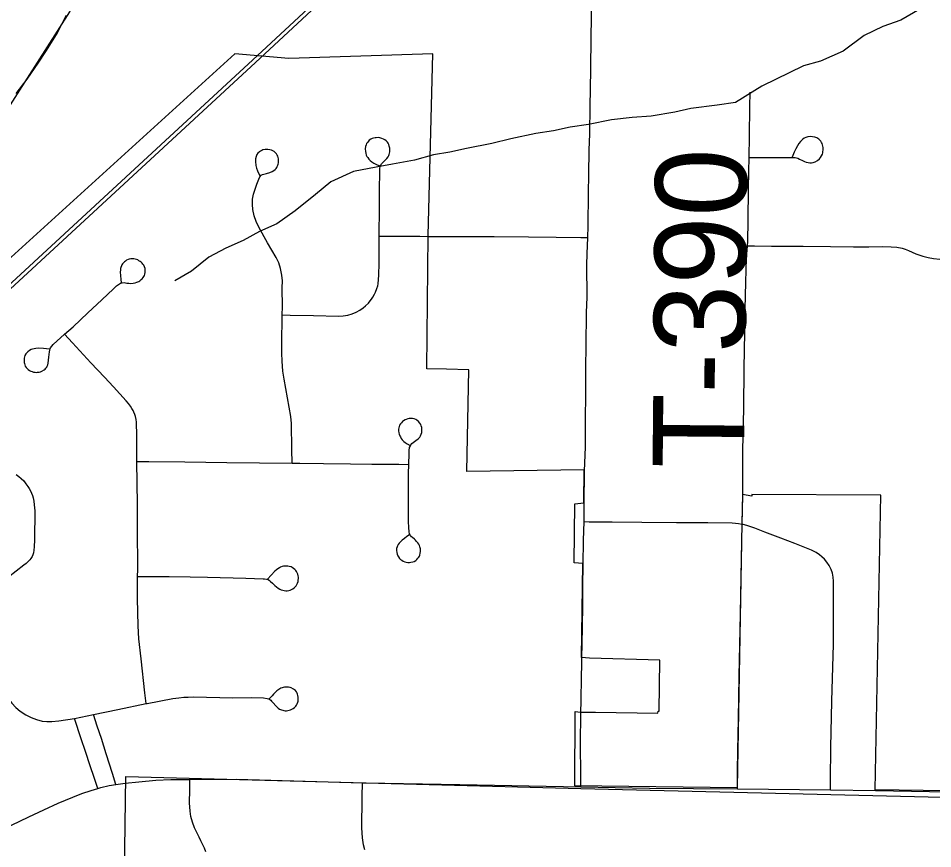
# Model space of a CAD drawing. Extents: x 0 to 34, y 0 to 22.
# Drawn here: x 4.409 to 4.977, y 17.868 to 18.383 of the extents above; entities that cross this region are included whole.
import ezdxf

# ---------------------------------------------------------------- set-up
doc = ezdxf.new("R2010")
doc.units = 0
for name, color, linetype in [('GM_X_City_Street', 7, 'Continuous'), ('GM_X_Corporation', 7, 'Continuous'), ('GM_X_Minor_River', 7, 'Continuous'), ('GM_X_Rail_Line', 7, 'Continuous'), ('GM_X_State_Route', 7, 'Continuous'), ('GM_X_Township_Road', 7, 'Continuous'), ('GM_X_Township_Road_Text', 7, 'Continuous')]:
    doc.layers.add(name, color=color, linetype=linetype)

msp = doc.modelspace()

# ---------------------------------------------------------------- linework, layer by layer
at = {"layer": 'GM_X_City_Street'}
for points in [[(4.57273, 18.19914), (4.5777, 18.19903), (4.59211, 18.19873), (4.60764, 18.19835), (4.61059, 18.19848), (4.61348, 18.19903), (4.61623, 18.19984), (4.61872, 18.20093), (4.62085, 18.20203), (4.62292, 18.20349), (4.62456, 18.20487), (4.62626, 18.20649), (4.6274, 18.2078), (4.62826, 18.2089), (4.6291, 18.21022), (4.63009, 18.21194), (4.63074, 18.21333), (4.6316, 18.21554), (4.63202, 18.21717), (4.63227, 18.21843), (4.63254, 18.22108), (4.63269, 18.22373), (4.63288, 18.23129), (4.63302, 18.24809), (4.63303, 18.24975), (4.63315, 18.26406), (4.63312, 18.2771), (4.63334, 18.28743), (4.63345, 18.28974), (4.63363, 18.29144), (4.63394, 18.29217), (4.63442, 18.29284), (4.63534, 18.29387), (4.63652, 18.29502), (4.63773, 18.29627), (4.63854, 18.29732), (4.63886, 18.29802), (4.6391, 18.29867), (4.63931, 18.29954), (4.63948, 18.30033), (4.63956, 18.30139), (4.63947, 18.30267), (4.63923, 18.3039), (4.6389, 18.30485), (4.63845, 18.30571), (4.63803, 18.30637), (4.63738, 18.30711), (4.63655, 18.30781), (4.63569, 18.30826), (4.63467, 18.30867), (4.63326, 18.30904), (4.63232, 18.30916), (4.63109, 18.30911), (4.63043, 18.30904), (4.6295, 18.30888), (4.62869, 18.30863), (4.62787, 18.30825), (4.6268, 18.30751), (4.62623, 18.30698), (4.62561, 18.30623), (4.62516, 18.3055), (4.6248, 18.30477), (4.62444, 18.30376), (4.62426, 18.30215), (4.62438, 18.30048), (4.62459, 18.29946), (4.62496, 18.29834), (4.62537, 18.29748), (4.62585, 18.29678), (4.62661, 18.2958), (4.62741, 18.29494), (4.62836, 18.29414), (4.62957, 18.29329), (4.63084, 18.2926), (4.63309, 18.29162)], [(4.57897, 18.10717), (4.57882, 18.11572), (4.57852, 18.1318), (4.57804, 18.13609), (4.57403, 18.15933), (4.57324, 18.16427), (4.57267, 18.17051), (4.57249, 18.17551), (4.57247, 18.18486), (4.57263, 18.19482), (4.57273, 18.19914), (4.57284, 18.20413), (4.5728, 18.21596), (4.57284, 18.22026), (4.57252, 18.22386), (4.57169, 18.22803), (4.57058, 18.23147), (4.56907, 18.23475), (4.5637, 18.24383), (4.55821, 18.25362), (4.55662, 18.2571), (4.55539, 18.26071), (4.55455, 18.26447), (4.55425, 18.26769), (4.55442, 18.27092), (4.55499, 18.27409), (4.55601, 18.27718), (4.55704, 18.28022), (4.5582, 18.28341), (4.5589, 18.28488), (4.55966, 18.28582), (4.56048, 18.28636), (4.56126, 18.28656), (4.56307, 18.28689), (4.56505, 18.28743), (4.5665, 18.28807), (4.56753, 18.28868), (4.56829, 18.28932), (4.56891, 18.28994), (4.56932, 18.2906), (4.56966, 18.29119), (4.56998, 18.29199), (4.57024, 18.29273), (4.57043, 18.2936), (4.57051, 18.29438), (4.57055, 18.29524), (4.57043, 18.29604), (4.57027, 18.29689), (4.56999, 18.29762), (4.56961, 18.29837), (4.5692, 18.29907), (4.56862, 18.29981), (4.56779, 18.30051), (4.56695, 18.30101), (4.56603, 18.30141), (4.56516, 18.30166), (4.56385, 18.30179), (4.56311, 18.30186), (4.56223, 18.30179), (4.56083, 18.30155), (4.5601, 18.30128), (4.55927, 18.30085), (4.55858, 18.30038), (4.55773, 18.29961), (4.55706, 18.29865), (4.55657, 18.29744), (4.55628, 18.29602), (4.55618, 18.29442), (4.55641, 18.29186), (4.55682, 18.29022), (4.55735, 18.28866), (4.55888, 18.28553)], [(4.42838, 18.17791), (4.42451, 18.17823), (4.4217, 18.17842), (4.41986, 18.17828), (4.41871, 18.17815), (4.41781, 18.17791), (4.41691, 18.17762), (4.41591, 18.17706), (4.41489, 18.17634), (4.4142, 18.17567), (4.41356, 18.17494), (4.41304, 18.17391), (4.41276, 18.17317), (4.41255, 18.17223), (4.41251, 18.17132), (4.41251, 18.17046), (4.41264, 18.16956), (4.41279, 18.16891), (4.41304, 18.16815), (4.4133, 18.16743), (4.41382, 18.16655), (4.41443, 18.16586), (4.41514, 18.1652), (4.41581, 18.16472), (4.41666, 18.16425), (4.4175, 18.16395), (4.41843, 18.16367), (4.41934, 18.16356), (4.42024, 18.16351), (4.42091, 18.16353), (4.42189, 18.16364), (4.42271, 18.1638), (4.42355, 18.16415), (4.42497, 18.165), (4.42559, 18.16549), (4.42612, 18.16602), (4.42666, 18.16672), (4.42695, 18.1673), (4.42728, 18.16816), (4.42753, 18.16912), (4.42776, 18.17113), (4.42797, 18.17297), (4.42829, 18.17618), (4.42851, 18.17734), (4.42871, 18.17808), (4.429, 18.17874), (4.42966, 18.17972), (4.43063, 18.18084), (4.43769, 18.18713), (4.44298, 18.19185), (4.45202, 18.20039), (4.46073, 18.20859), (4.46796, 18.21541), (4.46996, 18.21725), (4.47106, 18.2181), (4.47233, 18.21884), (4.47338, 18.21916), (4.4747, 18.21926), (4.47622, 18.21893), (4.4775, 18.21881), (4.47871, 18.21875), (4.48017, 18.21889), (4.48153, 18.2191), (4.48261, 18.21942), (4.48383, 18.21996), (4.48446, 18.22037), (4.48527, 18.22103), (4.48593, 18.22159), (4.48642, 18.22227), (4.48692, 18.22297), (4.4872, 18.22367), (4.48746, 18.22449), (4.48761, 18.22539), (4.48772, 18.22612), (4.48774, 18.227), (4.48761, 18.22799), (4.48733, 18.22897), (4.48687, 18.22992), (4.48629, 18.2307), (4.48584, 18.23127), (4.4852, 18.23181), (4.48449, 18.23239), (4.48385, 18.2328), (4.48304, 18.23329), (4.48226, 18.23362), (4.48152, 18.23382), (4.48068, 18.23396), (4.47971, 18.23399), (4.47889, 18.2339), (4.47782, 18.23366), (4.47704, 18.23345), (4.47618, 18.23304), (4.47552, 18.23258), (4.4749, 18.23209), (4.47416, 18.23144), (4.47363, 18.23078), (4.4733, 18.23024), (4.47293, 18.22962), (4.4726, 18.22864), (4.47244, 18.22789), (4.47233, 18.22712), (4.47223, 18.22564), (4.47228, 18.22357), (4.4725, 18.22116), (4.47281, 18.21922)], [(4.48823, 17.95798), (4.4875, 17.96457), (4.48514, 17.98573), (4.48383, 17.99814), (4.48332, 18.00624), (4.48295, 18.02308), (4.48303, 18.03677), (4.48305, 18.04113), (4.48295, 18.06727), (4.48288, 18.08158), (4.4826, 18.1082), (4.48257, 18.11085), (4.48253, 18.12633), (4.4824, 18.13035), (4.48231, 18.13253), (4.48206, 18.13425), (4.48173, 18.13603), (4.48131, 18.13738), (4.4807, 18.13883), (4.48014, 18.13993), (4.47938, 18.14117), (4.47856, 18.14245), (4.47737, 18.14417), (4.47591, 18.1458), (4.46796, 18.15454), (4.46251, 18.16047), (4.45388, 18.16944), (4.44251, 18.18186), (4.43769, 18.18713)], [(4.65175, 18.06272), (4.65012, 18.06157), (4.64865, 18.06043), (4.64716, 18.05929), (4.64637, 18.05863), (4.6453, 18.05749), (4.64477, 18.05669), (4.64432, 18.05592), (4.64404, 18.05516), (4.64379, 18.05414), (4.64371, 18.05293), (4.64384, 18.05177), (4.6441, 18.05067), (4.64444, 18.04973), (4.64491, 18.04894), (4.64554, 18.04807), (4.64624, 18.0474), (4.64694, 18.04688), (4.64787, 18.04627), (4.64886, 18.04588), (4.6498, 18.04568), (4.65072, 18.04557), (4.65183, 18.04555), (4.6527, 18.04563), (4.65379, 18.04584), (4.65463, 18.04619), (4.65562, 18.04674), (4.65637, 18.04737), (4.65705, 18.04814), (4.65761, 18.04886), (4.65795, 18.04954), (4.65818, 18.05014), (4.65841, 18.05122), (4.65858, 18.05231), (4.6586, 18.05321), (4.65851, 18.0541), (4.65829, 18.0552), (4.65798, 18.056), (4.65755, 18.05693), (4.65698, 18.05776), (4.65622, 18.05865), (4.65552, 18.05943), (4.65481, 18.0601), (4.65357, 18.06102), (4.65295, 18.06155), (4.65242, 18.06222), (4.65209, 18.06275), (4.65183, 18.06332), (4.65149, 18.06462), (4.65131, 18.06729), (4.65106, 18.071), (4.65106, 18.09211), (4.65119, 18.10082), (4.65134, 18.1064), (4.65153, 18.11322), (4.65159, 18.11503), (4.65187, 18.11689), (4.65209, 18.11759), (4.65257, 18.11846), (4.65328, 18.11932), (4.65404, 18.11995), (4.65569, 18.12114), (4.65708, 18.12228), (4.6581, 18.12325), (4.65869, 18.12419), (4.65912, 18.12512), (4.65935, 18.12616), (4.65946, 18.12726), (4.65946, 18.12802), (4.65935, 18.12935), (4.65908, 18.1303), (4.65877, 18.13117), (4.65818, 18.13208), (4.6574, 18.13302), (4.65642, 18.13379), (4.65564, 18.13425), (4.65475, 18.13471), (4.65359, 18.13487), (4.65252, 18.13482), (4.6516, 18.13478), (4.65075, 18.13462), (4.64979, 18.13434), (4.64903, 18.134), (4.64812, 18.1335), (4.64738, 18.13297), (4.64671, 18.13229), (4.64615, 18.13162), (4.64567, 18.13075), (4.64528, 18.12997), (4.6451, 18.129), (4.645, 18.12816), (4.64502, 18.12716), (4.64517, 18.12604), (4.64544, 18.12515), (4.64574, 18.12422), (4.6461, 18.12347), (4.64669, 18.12253), (4.6473, 18.12166), (4.6483, 18.12058), (4.64899, 18.11998), (4.65039, 18.11912), (4.65212, 18.11821)], [(4.4826, 18.1082), (4.49, 18.10814), (4.51237, 18.10794), (4.53845, 18.10761), (4.57897, 18.10717), (4.58369, 18.10712), (4.59837, 18.10697), (4.61519, 18.10679), (4.62836, 18.10664), (4.64517, 18.10646), (4.65134, 18.1064)], [(4.40765, 18.10016), (4.40928, 18.09896), (4.41079, 18.09772), (4.4123, 18.0961), (4.41366, 18.09443), (4.41479, 18.09275), (4.41566, 18.0914), (4.41652, 18.08994), (4.41716, 18.08858), (4.41766, 18.08713), (4.41811, 18.08561), (4.41853, 18.08367), (4.41886, 18.08132), (4.41913, 18.0776), (4.41894, 18.05954), (4.41878, 18.05518), (4.41865, 18.05313), (4.41832, 18.05162), (4.418, 18.05032), (4.41752, 18.04919), (4.41681, 18.04806), (4.41611, 18.04719), (4.41508, 18.0461), (4.41382, 18.04494), (4.41243, 18.04378), (4.40281, 18.03632)], [(4.91304, 17.90436), (4.91308, 17.91038), (4.91324, 17.93078), (4.91401, 17.95941), (4.91489, 17.99493), (4.91488, 18.00609), (4.91488, 18.01642), (4.91505, 18.0292), (4.91499, 18.03397), (4.91475, 18.03636), (4.91428, 18.03892), (4.9135, 18.04125), (4.9123, 18.0437), (4.91087, 18.04567), (4.90932, 18.04758), (4.90765, 18.04913), (4.90627, 18.05032), (4.90413, 18.05176), (4.90125, 18.05324), (4.89099, 18.05724), (4.88226, 18.06061), (4.87238, 18.06442), (4.86604, 18.06683), (4.86185, 18.06824), (4.85833, 18.06934)], [(4.48303, 18.03677), (4.49007, 18.0368), (4.5025, 18.03686), (4.51555, 18.03662), (4.52641, 18.03632), (4.55026, 18.03577), (4.56088, 18.03547), (4.56187, 18.03539), (4.56302, 18.03522), (4.56401, 18.03493), (4.56483, 18.0344), (4.56553, 18.03378), (4.56664, 18.03268), (4.56812, 18.03124), (4.56923, 18.03033), (4.57026, 18.02959), (4.57135, 18.02901), (4.57216, 18.02864), (4.57308, 18.02834), (4.57388, 18.02815), (4.57491, 18.02804), (4.57594, 18.02803), (4.57677, 18.02817), (4.5777, 18.0284), (4.57853, 18.02869), (4.57935, 18.02914), (4.58013, 18.02972), (4.58079, 18.03033), (4.58136, 18.0311), (4.5819, 18.0319), (4.58227, 18.03273), (4.5826, 18.03363), (4.58276, 18.03453), (4.58289, 18.03552), (4.58284, 18.03642), (4.58272, 18.03729), (4.58243, 18.03821), (4.58214, 18.03901), (4.58162, 18.03988), (4.5812, 18.04054), (4.58054, 18.04123), (4.5798, 18.04189), (4.57891, 18.04238), (4.57823, 18.04276), (4.57718, 18.04307), (4.57634, 18.04325), (4.57534, 18.04332), (4.57457, 18.04333), (4.57349, 18.04316), (4.57276, 18.04296), (4.57172, 18.04259), (4.57099, 18.04226), (4.57009, 18.04169), (4.56931, 18.04107), (4.56828, 18.04016), (4.56368, 18.03522)], [(4.39756, 17.98059), (4.39744, 17.97976), (4.39728, 17.97829), (4.39723, 17.9768), (4.39728, 17.97539), (4.39744, 17.97383), (4.39768, 17.97232), (4.39804, 17.9709), (4.39916, 17.96748), (4.3999, 17.96565), (4.4007, 17.9642), (4.40149, 17.96278), (4.4026, 17.96112), (4.40483, 17.95826), (4.40731, 17.9556), (4.41009, 17.9533), (4.41364, 17.95098), (4.41687, 17.94929), (4.42024, 17.948), (4.42373, 17.94712), (4.42671, 17.94677), (4.42969, 17.9468), (4.43406, 17.94728), (4.44377, 17.94869)], [(4.44377, 17.94869), (4.45557, 17.95112), (4.47067, 17.95422), (4.48823, 17.95798), (4.4889, 17.95812), (4.50481, 17.96108), (4.50853, 17.96163), (4.51165, 17.96193), (4.51444, 17.96201), (4.51765, 17.9621), (4.54211, 17.9616), (4.55368, 17.9617), (4.56119, 17.96146), (4.56336, 17.96119), (4.56429, 17.96096), (4.56498, 17.96054), (4.56569, 17.96006), (4.56612, 17.95957), (4.56715, 17.95837), (4.56874, 17.95648), (4.57019, 17.95523), (4.57116, 17.95459), (4.57223, 17.95405), (4.57306, 17.95381), (4.5738, 17.95366), (4.57466, 17.95356), (4.57542, 17.95357), (4.57634, 17.95369), (4.57703, 17.95386), (4.57791, 17.95414), (4.57881, 17.95451), (4.57964, 17.95501), (4.58046, 17.95563), (4.58116, 17.95637), (4.58165, 17.95706), (4.58214, 17.95789), (4.58243, 17.95875), (4.58259, 17.95957), (4.58268, 17.9604), (4.58266, 17.96104), (4.58264, 17.96188), (4.58247, 17.9629), (4.58227, 17.96373), (4.58199, 17.96454), (4.58153, 17.96529), (4.58099, 17.96599), (4.58041, 17.96653), (4.57971, 17.96702), (4.57836, 17.96771), (4.57762, 17.96796), (4.57671, 17.96813), (4.57589, 17.96821), (4.5749, 17.96821), (4.57424, 17.96817), (4.57342, 17.968), (4.57276, 17.96779), (4.57198, 17.96746), (4.57074, 17.96677), (4.56951, 17.96586), (4.56807, 17.96454), (4.56728, 17.96373), (4.56643, 17.96286), (4.56474, 17.96092)], [(4.45825, 17.90534), (4.45598, 17.91211), (4.4536, 17.91925), (4.45057, 17.92832), (4.44799, 17.93603), (4.44377, 17.94869)], [(4.46946, 17.90783), (4.46732, 17.91468), (4.46356, 17.92674), (4.46055, 17.93622), (4.45799, 17.94387), (4.45557, 17.95112)], [(4.52528, 17.86597), (4.52442, 17.86821), (4.52346, 17.87035), (4.52228, 17.8728), (4.52111, 17.87515), (4.51994, 17.87761), (4.51828, 17.88097), (4.51705, 17.88433), (4.51608, 17.88785), (4.51555, 17.89127), (4.51523, 17.89629), (4.51533, 17.90441), (4.51541, 17.91092)], [(4.62408, 17.86716), (4.62324, 17.87024), (4.62259, 17.87466), (4.62219, 17.88094), (4.62222, 17.88659), (4.62244, 17.89341), (4.62247, 17.90022), (4.6225, 17.90886)]]:
    msp.add_lwpolyline(points, dxfattribs=at)
at = {"layer": 'GM_X_Corporation'}
msp.add_lwpolyline([(4.98559, 17.90373), (4.94083, 17.90452), (4.9444, 18.08728), (4.86422, 18.08769), (4.86419, 18.08658), (4.85841, 18.08768), (4.8581, 18.0699), (4.85524, 17.90572), (4.75441, 17.90688), (4.75458, 17.95302), (4.75789, 17.95267), (4.76727, 17.95256), (4.80603, 17.95209), (4.80604, 17.95323), (4.80676, 17.95322), (4.80723, 17.98485), (4.76347, 17.98625), (4.75862, 17.98648), (4.75933, 18.0448), (4.75391, 18.04526), (4.75437, 18.08199), (4.75989, 18.08256), (4.76022, 18.10304), (4.68735, 18.10203), (4.68851, 18.16517), (4.67476, 18.16541), (4.66252, 18.16563), (4.66336, 18.24846), (4.66621, 18.36114), (4.57678, 18.3582), (4.54341, 18.36112), (4.081, 17.94135)], dxfattribs=at)
msp.add_lwpolyline([(4.75823, 17.90529), (4.98239, 17.89994), (5.48857, 17.88606), (5.47838, 16.95118), (4.45758, 16.96884), (4.4689, 17.41819), (4.47574, 17.91277)], close=True, dxfattribs=at)
at = {"layer": 'GM_X_Minor_River'}
msp.add_lwpolyline([(4.9685, 18.38879), (4.9567, 18.38211), (4.94569, 18.37807), (4.93391, 18.37253), (4.92094, 18.36282), (4.90688, 18.35654), (4.89627, 18.35364), (4.87042, 18.34106), (4.85404, 18.33102), (4.84269, 18.32926), (4.82642, 18.32719), (4.81657, 18.32503), (4.8018, 18.32256), (4.79008, 18.32157), (4.77722, 18.32021), (4.76282, 18.31736), (4.75147, 18.3156), (4.74124, 18.31345), (4.73026, 18.31169), (4.71473, 18.30847), (4.70298, 18.30558), (4.68708, 18.30237), (4.67685, 18.30022), (4.66662, 18.29845), (4.65487, 18.29518), (4.64124, 18.29269), (4.63102, 18.29092), (4.617, 18.28806), (4.60294, 18.28179), (4.5934, 18.27394), (4.5808, 18.26384), (4.56936, 18.25564), (4.55872, 18.25084), (4.54845, 18.24527), (4.53781, 18.24047), (4.52716, 18.23491), (4.51647, 18.22631), (4.5062, 18.22037)], dxfattribs=at)
at = {"layer": 'GM_X_Rail_Line'}
for points in [[(4.0369, 17.87629), (4.0405, 17.87963), (4.10582, 17.94022), (4.26502, 18.087), (4.55609, 18.35576), (4.76707, 18.55171), (4.9213, 18.69505), (5.34845, 19.09084), (6.00629, 19.70228), (6.04051, 19.73365)], [(4.26344, 18.0887), (4.5545, 18.35746), (4.76549, 18.55341), (4.91971, 18.69674), (5.34686, 19.09254), (6.00471, 19.70399), (6.03893, 19.73535)], [(2.20624, 17.40963), (2.27317, 17.34884), (2.53129, 17.30267), (2.6424, 17.31122), (3.24752, 17.60363), (3.90003, 17.91971), (3.99131, 17.98254), (4.33797, 18.26064), (4.40078, 18.3243), (4.44097, 18.38712), (4.46358, 18.43738), (4.47865, 18.49769), (4.49623, 18.5312), (4.52052, 18.56387), (4.5582, 18.59821), (4.78429, 18.80343)]]:
    msp.add_lwpolyline(points, dxfattribs=at)
at = {"layer": 'GM_X_State_Route'}
for points in [[(4.40759, 18.33651), (4.4144, 18.34548), (4.42129, 18.35529), (4.42593, 18.36251), (4.43257, 18.37322), (4.4388, 18.38511)], [(4.22426, 17.79485), (4.33638, 17.84912), (4.34708, 17.85453), (4.36746, 17.86483), (4.41558, 17.88775), (4.42474, 17.89204), (4.43371, 17.89614), (4.44286, 17.89995), (4.44842, 17.90209), (4.45426, 17.90414), (4.45825, 17.90534), (4.46011, 17.9059), (4.4653, 17.90711), (4.46946, 17.90783), (4.47531, 17.90863), (4.48378, 17.90942), (4.49421, 17.9104), (4.50357, 17.91089), (4.51541, 17.91092), (4.5443, 17.911), (4.6225, 17.90886), (4.62479, 17.90879), (4.68293, 17.90774)], [(4.68293, 17.90774), (4.75809, 17.90625), (4.80073, 17.90541), (4.85547, 17.90517)], [(4.85547, 17.90517), (4.91304, 17.90436), (4.94105, 17.90396)], [(4.94105, 17.90396), (4.98581, 17.90317), (4.99531, 17.903), (5.07642, 17.9018), (5.08926, 17.90161), (5.23963, 17.89857)]]:
    msp.add_lwpolyline(points, dxfattribs=at)
at = {"layer": 'GM_X_Township_Road'}
for p, q in [((4.85833, 18.06934), (4.85864, 18.08713)), ((4.75812, 17.95212), (4.75828, 17.96001))]:
    msp.add_line(p, q, dxfattribs=at)
for points in [[(4.7624, 18.24722), (4.76259, 18.25417), (4.76284, 18.2749), (4.76308, 18.28617), (4.7634, 18.30164), (4.76364, 18.31134), (4.76388, 18.32919), (4.76404, 18.3389), (4.76428, 18.35223), (4.7646, 18.37065), (4.76484, 18.38414), (4.76508, 18.40035), (4.76524, 18.41483), (4.7654, 18.42288)], [(4.8626, 18.29684), (4.86278, 18.31005), (4.86304, 18.32837), (4.86317, 18.33732)], [(4.8626, 18.29684), (4.86621, 18.29683), (4.87312, 18.29681), (4.88185, 18.2968), (4.88851, 18.29678), (4.89122, 18.29673), (4.89283, 18.29639), (4.89391, 18.2959), (4.89569, 18.29495), (4.89691, 18.29439), (4.89803, 18.29393), (4.89918, 18.29372), (4.90038, 18.2936), (4.90141, 18.2936), (4.90239, 18.29376), (4.90356, 18.29415), (4.90498, 18.29492), (4.9062, 18.29601), (4.90692, 18.29681), (4.90758, 18.29788), (4.90807, 18.29887), (4.90832, 18.29977), (4.90844, 18.30054), (4.90856, 18.3013), (4.90861, 18.30221), (4.90856, 18.30302), (4.90843, 18.30386), (4.90823, 18.30463), (4.90791, 18.30543), (4.90761, 18.3061), (4.90708, 18.30689), (4.90658, 18.3075), (4.90584, 18.30816), (4.90457, 18.30894), (4.90338, 18.30943), (4.90194, 18.30976), (4.90049, 18.30985), (4.89901, 18.30964), (4.8977, 18.30927), (4.89673, 18.30873), (4.89589, 18.30815), (4.89523, 18.30754), (4.89445, 18.30668), (4.8935, 18.30546), (4.89256, 18.30409), (4.89157, 18.30231), (4.89055, 18.30009), (4.88935, 18.29701)], [(4.86158, 18.24199), (4.86177, 18.24471), (4.86198, 18.25784), (4.8623, 18.27745), (4.86247, 18.28813), (4.8626, 18.29684)], [(4.63302, 18.24809), (4.63611, 18.24807), (4.64336, 18.24803), (4.65137, 18.24798), (4.65813, 18.24794), (4.66359, 18.24791)], [(4.66359, 18.24791), (4.6758, 18.24788), (4.68888, 18.24784), (4.70426, 18.2478), (4.72573, 18.24758), (4.74276, 18.24742), (4.75806, 18.24726), (4.7624, 18.24722)], [(4.76043, 18.10159), (4.76044, 18.10249), (4.76101, 18.11705), (4.76108, 18.13374), (4.76133, 18.15045), (4.76132, 18.1664), (4.76139, 18.18006), (4.76163, 18.20062), (4.76196, 18.21025), (4.76195, 18.23021), (4.76211, 18.23706), (4.7624, 18.24722)], [(4.85864, 18.08713), (4.85868, 18.09873), (4.85875, 18.11518), (4.85922, 18.14114), (4.85959, 18.1661), (4.85992, 18.18831), (4.8602, 18.20273), (4.86063, 18.21947), (4.86105, 18.23447), (4.86158, 18.24199)], [(4.86158, 18.24199), (4.86602, 18.24195), (4.8765, 18.24187), (4.89623, 18.24171), (4.91309, 18.24158), (4.92732, 18.24146), (4.93698, 18.24138), (4.94551, 18.24154), (4.95077, 18.2413), (4.95438, 18.24113), (4.9576, 18.24056), (4.95949, 18.2399), (4.96154, 18.23908), (4.96617, 18.23708), (4.97051, 18.23554), (4.97372, 18.23472), (4.97701, 18.23415), (4.98088, 18.23382), (4.98828, 18.23325), (4.9908, 18.23305)], [(4.76012, 18.082), (4.76021, 18.08809), (4.76034, 18.09624), (4.76043, 18.10159)], [(4.76016, 18.07086), (4.76021, 18.07303), (4.76012, 18.082)], [(4.75956, 18.04425), (4.75988, 18.05922), (4.76016, 18.07086)], [(4.76016, 18.07086), (4.76335, 18.07084), (4.77752, 18.07072), (4.79602, 18.07057), (4.81745, 18.07041), (4.83692, 18.07025), (4.85206, 18.07013), (4.85416, 18.07001), (4.85592, 18.0698), (4.85833, 18.06934)], [(4.85547, 17.90517), (4.85541, 17.91595), (4.85564, 17.92895), (4.85598, 17.94836), (4.85638, 17.97509), (4.85727, 18.01376), (4.85786, 18.04779), (4.85833, 18.06934)], [(4.75885, 17.98592), (4.75916, 18.00493), (4.75932, 18.01973), (4.7594, 18.03076), (4.75956, 18.04425)], [(4.75828, 17.96001), (4.75836, 17.96347), (4.75852, 17.97088), (4.75885, 17.98592)], [(4.75809, 17.90625), (4.75805, 17.91354), (4.75796, 17.93303), (4.75812, 17.95212)]]:
    msp.add_lwpolyline(points, dxfattribs=at)

# ---------------------------------------------------------------- texts
at = {"layer": 'GM_X_Township_Road_Text'}
msp.add_text('T-390', height=0.056818, rotation=89.4424, dxfattribs=at).set_placement((4.85944, 18.1037))

doc.saveas('drawing.dxf')
